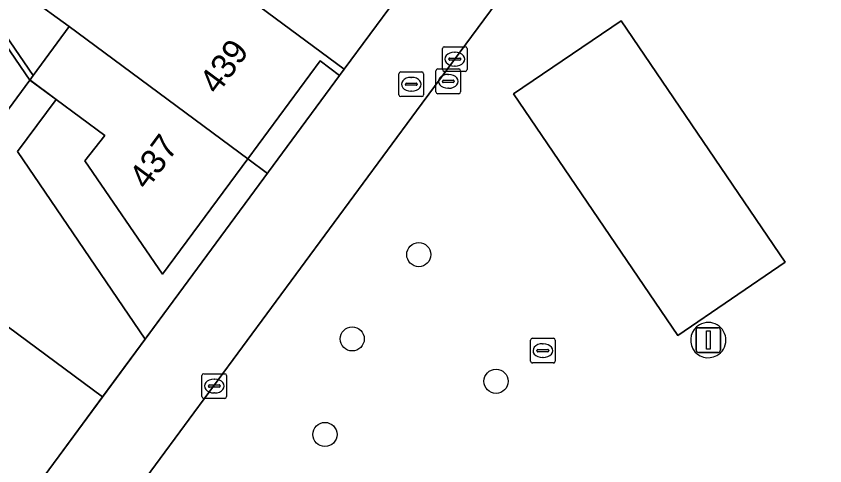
# Model space of a CAD drawing. Extents: x 155275 to 156265, y 382654 to 383635.
# Drawn here: x 155773.29 to 155806.09, y 383268.44 to 383286.66 of the extents above; entities that cross this region are included whole.
import ezdxf

# ---------------------------------------------------------------- set-up
doc = ezdxf.new("R2010")
doc.units = 0
for name, color, linetype in [('IMGEO_Boom', 7, 'Continuous'), ('IMGEO_Erf', 7, 'Continuous'), ('IMGEO_Kolk', 7, 'Continuous'), ('IMGEO_Lichtmast', 7, 'Continuous'), ('IMGEO_Muur', 7, 'Continuous'), ('IMGEO_Pand', 7, 'Continuous'), ('IMGEO_Pand_nummerreeks', 7, 'Continuous'), ('IMGEO_Pand_overbouw', 7, 'Continuous'), ('IMGEO_Parkeervlak_open', 7, 'Continuous'), ('IMGEO_Rijbaan_lokaal_open', 7, 'Continuous'), ('IMGEO_Rioolput', 7, 'Continuous'), ('IMGEO_Terreindeel_gesloten', 7, 'Continuous'), ('IMGEO_Voetpad_open', 7, 'Continuous')]:
    doc.layers.add(name, color=color, linetype=linetype)

msp = doc.modelspace()

# ---------------------------------------------------------------- linework, layer by layer
at = {"layer": 'IMGEO_Boom'}
for centre in [(155789.62, 383277), (155786.919, 383273.583), (155792.753, 383271.865), (155785.813, 383269.709)]:
    msp.add_circle(centre, 0.489, dxfattribs=at)
at = {"layer": 'IMGEO_Erf'}
msp.add_lwpolyline([(155766.346, 383295.405), (155773.979, 383284.258), (155775.431, 383286.243), (155773.822, 383287.426), (155776.948, 383291.655), (155780.069, 383295.876), (155783.19, 383300.098), (155786.313, 383304.323), (155789.463, 383308.585), (155792.614, 383312.847), (155795.763, 383317.106)], dxfattribs=at)
at = {"layer": 'IMGEO_Kolk'}
for p, q in [((155790.579, 383284.499), (155790.579, 383285.351)), ((155790.654, 383285.425), (155791.506, 383285.425)), ((155791.067, 383285.205), (155791.092, 383285.205)), ((155791.58, 383285.351), (155791.58, 383284.499)), ((155790.838, 383284.919), (155790.838, 383284.931)), ((155791.276, 383284.882), (155790.878, 383284.882)), ((155790.881, 383284.968), (155791.279, 383284.968)), ((155791.322, 383284.931), (155791.322, 383284.919)), ((155791.09, 383284.645), (155791.065, 383284.645)), ((155791.506, 383284.425), (155790.654, 383284.425)), ((155794.153, 383272.681), (155794.153, 383273.533)), ((155794.228, 383273.607), (155795.08, 383273.607)), ((155794.641, 383273.387), (155794.666, 383273.387)), ((155795.154, 383273.533), (155795.154, 383272.681)), ((155794.412, 383273.101), (155794.412, 383273.113)), ((155794.85, 383273.064), (155794.452, 383273.064)), ((155794.455, 383273.15), (155794.853, 383273.15)), ((155794.896, 383273.113), (155794.896, 383273.101)), ((155794.664, 383272.827), (155794.639, 383272.827)), ((155795.08, 383272.607), (155794.228, 383272.607)), ((155780.824, 383271.247), (155780.824, 383272.099)), ((155780.899, 383272.173), (155781.751, 383272.173)), ((155781.825, 383272.099), (155781.825, 383271.247)), ((155781.083, 383271.667), (155781.083, 383271.679)), ((155781.126, 383271.716), (155781.524, 383271.716)), ((155781.312, 383271.953), (155781.337, 383271.953)), ((155781.567, 383271.679), (155781.567, 383271.667)), ((155781.521, 383271.63), (155781.123, 383271.63)), ((155781.335, 383271.393), (155781.31, 383271.393)), ((155781.751, 383271.173), (155780.899, 383271.173))]:
    msp.add_line(p, q, dxfattribs=at)
for points in [[(155790.579, 383284.499), (155790.579, 383285.351)], [(155790.654, 383285.425), (155791.506, 383285.425)], [(155791.58, 383285.351), (155791.58, 383284.499)], [(155791.506, 383284.425), (155790.654, 383284.425)], [(155794.153, 383272.681), (155794.153, 383273.533)], [(155794.228, 383273.607), (155795.08, 383273.607)], [(155795.154, 383273.533), (155795.154, 383272.681)], [(155795.08, 383272.607), (155794.228, 383272.607)], [(155780.824, 383271.247), (155780.824, 383272.099)], [(155780.899, 383272.173), (155781.751, 383272.173)], [(155781.825, 383272.099), (155781.825, 383271.247)], [(155781.751, 383271.173), (155780.899, 383271.173)]]:
    msp.add_lwpolyline(points, dxfattribs=at)
for centre, radius, start, end in [((155790.656, 383285.349), 0.0765, 91.552, 178.448), ((155790.656, 383285.349), 0.0765, 91.552, 178.448), ((155791.504, 383285.349), 0.0765, 1.552, 88.448), ((155791.504, 383285.349), 0.0765, 1.552, 88.448), ((155790.878, 383284.928), 0.0403, 85.8775, 175.7526), ((155790.875, 383284.918), 0.0366, 178.938, 274.7102), ((155791.279, 383284.925), 0.043, 264.8664, 352.4533), ((155791.283, 383284.93), 0.0386, 1.7309, 96.639), ((155790.656, 383284.501), 0.0765, 181.552, 268.448), ((155790.656, 383284.501), 0.0765, 181.552, 268.448), ((155791.504, 383284.501), 0.0765, 271.552, 358.448), ((155791.504, 383284.501), 0.0765, 271.552, 358.448), ((155794.23, 383273.531), 0.0765, 91.552, 178.448), ((155794.23, 383273.531), 0.0765, 91.552, 178.448), ((155795.078, 383273.531), 0.0765, 1.552, 88.448), ((155795.078, 383273.531), 0.0765, 1.552, 88.448), ((155794.452, 383273.11), 0.0403, 85.8775, 175.7526), ((155794.449, 383273.1), 0.0366, 178.938, 274.7102), ((155794.853, 383273.107), 0.043, 264.8664, 352.4533), ((155794.857, 383273.112), 0.0386, 1.7309, 96.639), ((155794.23, 383272.683), 0.0765, 181.552, 268.448), ((155794.23, 383272.683), 0.0765, 181.552, 268.448), ((155795.078, 383272.683), 0.0765, 271.552, 358.448), ((155795.078, 383272.683), 0.0765, 271.552, 358.448), ((155780.901, 383272.097), 0.0765, 91.552, 178.448), ((155780.901, 383272.097), 0.0765, 91.552, 178.448), ((155781.749, 383272.097), 0.0765, 1.552, 88.448), ((155781.749, 383272.097), 0.0765, 1.552, 88.448), ((155781.123, 383271.676), 0.0403, 85.8775, 175.7526), ((155781.528, 383271.678), 0.0386, 1.7309, 96.639), ((155781.12, 383271.666), 0.0366, 178.938, 274.7102), ((155781.524, 383271.673), 0.043, 264.8664, 352.4533), ((155780.901, 383271.249), 0.0765, 181.552, 268.448), ((155780.901, 383271.249), 0.0765, 181.552, 268.448), ((155781.749, 383271.249), 0.0765, 271.552, 358.448), ((155781.749, 383271.249), 0.0765, 271.552, 358.448)]:
    msp.add_arc(centre, radius, start, end, dxfattribs=at)
for centre, major_axis, ratio, start_param, end_param in [((155791.066, 383284.925), (-0.387, 0.002), 0.722429, 4.712389, 7.853982), ((155791.091, 383284.925), (-0.39, 0.002), 0.717154, 1.570796, 4.712389), ((155794.64, 383273.107), (-0.387, 0.002), 0.722429, 4.712389, 7.853982), ((155794.665, 383273.107), (-0.39, 0.002), 0.717154, 1.570796, 4.712389), ((155781.311, 383271.673), (-0.387, 0.002), 0.722429, 4.712389, 7.853982), ((155781.336, 383271.673), (-0.39, 0.002), 0.717154, 1.570796, 4.712389)]:
    msp.add_ellipse(centre, major_axis=major_axis, ratio=ratio, start_param=start_param, end_param=end_param, dxfattribs=at)
at = {"layer": 'IMGEO_Lichtmast'}
for p, q in [((155800.969, 383274.036), (155801.759, 383274.036)), ((155801.759, 383274.036), (155800.969, 383274.036)), ((155800.869, 383273.136), (155800.869, 383273.936)), ((155800.869, 383273.936), (155800.869, 383273.136)), ((155801.859, 383273.936), (155801.859, 383273.136)), ((155801.859, 383273.136), (155801.859, 383273.936)), ((155801.759, 383273.036), (155800.969, 383273.036)), ((155800.969, 383273.036), (155801.759, 383273.036))]:
    msp.add_line(p, q, dxfattribs=at)
msp.add_lwpolyline([(155801.289, 383273.911), (155801.439, 383273.911), (155801.439, 383273.161), (155801.289, 383273.161), (155801.289, 383273.911)], dxfattribs=at)
for centre, start, end in [((155800.969, 383273.936), 90, 180), ((155800.969, 383273.936), 90, 180), ((155801.759, 383273.936), 0, 90), ((155801.759, 383273.936), 360, 90), ((155800.969, 383273.136), 180, 270), ((155800.969, 383273.136), 180, 270), ((155801.759, 383273.136), 270, 0), ((155801.759, 383273.136), 270, 0)]:
    msp.add_arc(centre, 0.1, start, end, dxfattribs=at)
at = {"layer": 'IMGEO_Muur'}
msp.add_lwpolyline([(155773.847, 383284.078), (155773.979, 383284.258), (155766.346, 383295.405), (155766.213, 383295.227)], close=True, dxfattribs=at)
at = {"layer": 'IMGEO_Pand'}
for points in [[(155789.72, 383288.742), (155780.069, 383295.876), (155776.948, 383291.655), (155786.598, 383284.52)], [(155775.431, 383286.243), (155782.682, 383280.882), (155785.615, 383284.849), (155786.405, 383284.259), (155786.598, 383284.52), (155776.948, 383291.655), (155773.822, 383287.426)], [(155775.431, 383286.243), (155773.979, 383284.258), (155773.847, 383284.078), (155774.904, 383283.294), (155776.886, 383281.823), (155776.079, 383280.798), (155779.225, 383276.207), (155782.682, 383280.882)]]:
    msp.add_lwpolyline(points, close=True, dxfattribs=at)
at = {"layer": 'IMGEO_Pand_overbouw'}
for points in [[(155782.682, 383280.882), (155783.479, 383280.293), (155786.405, 383284.259), (155785.615, 383284.849)], [(155776.886, 383281.823), (155774.904, 383283.294), (155773.836, 383284.086), (155768.735, 383277.191), (155776.792, 383271.232), (155783.479, 383280.293), (155782.682, 383280.882), (155779.225, 383276.207), (155776.079, 383280.798)], [(155771.65, 383264.258), (155776.792, 383271.232), (155768.735, 383277.191), (155762.039, 383268.14), (155762.867, 383267.527), (155766.131, 383271.951), (155766.263, 383272.13), (155769.629, 383267.192), (155768.939, 383266.259)]]:
    msp.add_lwpolyline(points, close=True, dxfattribs=at)
at = {"layer": 'IMGEO_Parkeervlak_open'}
msp.add_lwpolyline([(155797.829, 383286.482), (155793.468, 383283.515), (155800.125, 383273.728), (155804.486, 383276.694)], close=True, dxfattribs=at)
at = {"layer": 'IMGEO_Rijbaan_lokaal_open'}
msp.add_lwpolyline([(155849.638, 383246.563), (155829.44, 383276.11), (155811.913, 383301.75), (155819.677, 383316.264), (155817.087, 383320.059), (155811.131, 383312.082), (155798.256, 383294.644), (155789.533, 383282.828), (155777.762, 383266.885)], dxfattribs=at)
msp.add_lwpolyline([(155800.125, 383273.728), (155793.468, 383283.515), (155797.829, 383286.482), (155804.486, 383276.694)], close=True, dxfattribs=at)
for centre, start, end in [((155801.361, 383273.534), 119.6358, 299.1671), ((155801.364, 383273.536), 298.8814, 119.9215)]:
    msp.add_arc(centre, 0.714, start, end, dxfattribs=at)
at = {"layer": 'IMGEO_Rioolput'}
for p, q in [((155790.391, 383284.524), (155791.243, 383284.524)), ((155788.815, 383283.479), (155788.815, 383284.331)), ((155788.89, 383284.405), (155789.742, 383284.405)), ((155789.303, 383284.185), (155789.328, 383284.185)), ((155789.816, 383284.331), (155789.816, 383283.479)), ((155790.316, 383283.598), (155790.316, 383284.45)), ((155790.804, 383284.304), (155790.829, 383284.304)), ((155791.317, 383284.45), (155791.317, 383283.598)), ((155789.074, 383283.899), (155789.074, 383283.911)), ((155789.512, 383283.862), (155789.114, 383283.862)), ((155789.117, 383283.948), (155789.515, 383283.948)), ((155789.558, 383283.911), (155789.558, 383283.899)), ((155790.575, 383284.018), (155790.575, 383284.03)), ((155791.013, 383283.981), (155790.615, 383283.981)), ((155790.618, 383284.067), (155791.016, 383284.067)), ((155791.059, 383284.03), (155791.059, 383284.018)), ((155789.326, 383283.625), (155789.301, 383283.625)), ((155791.243, 383283.524), (155790.391, 383283.524)), ((155790.827, 383283.744), (155790.802, 383283.744)), ((155789.742, 383283.405), (155788.89, 383283.405))]:
    msp.add_line(p, q, dxfattribs=at)
for points in [[(155790.391, 383284.524), (155791.243, 383284.524)], [(155788.815, 383283.479), (155788.815, 383284.331)], [(155788.89, 383284.405), (155789.742, 383284.405)], [(155789.816, 383284.331), (155789.816, 383283.479)], [(155790.316, 383283.598), (155790.316, 383284.45)], [(155791.317, 383284.45), (155791.317, 383283.598)], [(155791.243, 383283.524), (155790.391, 383283.524)], [(155789.742, 383283.405), (155788.89, 383283.405)]]:
    msp.add_lwpolyline(points, dxfattribs=at)
for centre, radius, start, end in [((155790.393, 383284.448), 0.0765, 91.552, 178.448), ((155790.393, 383284.448), 0.0765, 91.552, 178.448), ((155791.241, 383284.448), 0.0765, 1.552, 88.448), ((155791.241, 383284.448), 0.0765, 1.552, 88.448), ((155788.892, 383284.329), 0.0765, 91.552, 178.448), ((155788.892, 383284.329), 0.0765, 91.552, 178.448), ((155789.74, 383284.329), 0.0765, 1.552, 88.448), ((155789.74, 383284.329), 0.0765, 1.552, 88.448), ((155789.114, 383283.908), 0.0403, 85.8775, 175.7526), ((155789.111, 383283.898), 0.0366, 178.938, 274.7102), ((155789.515, 383283.905), 0.043, 264.8664, 352.4533), ((155789.519, 383283.91), 0.0386, 1.7309, 96.639), ((155790.615, 383284.027), 0.0403, 85.8775, 175.7526), ((155790.612, 383284.017), 0.0366, 178.938, 274.7102), ((155791.016, 383284.024), 0.043, 264.8664, 352.4533), ((155791.02, 383284.029), 0.0386, 1.7309, 96.639), ((155788.892, 383283.481), 0.0765, 181.552, 268.448), ((155788.892, 383283.481), 0.0765, 181.552, 268.448), ((155789.74, 383283.481), 0.0765, 271.552, 358.448), ((155789.74, 383283.481), 0.0765, 271.552, 358.448), ((155790.393, 383283.6), 0.0765, 181.552, 268.448), ((155790.393, 383283.6), 0.0765, 181.552, 268.448), ((155791.241, 383283.6), 0.0765, 271.552, 358.448), ((155791.241, 383283.6), 0.0765, 271.552, 358.448)]:
    msp.add_arc(centre, radius, start, end, dxfattribs=at)
for centre, major_axis, ratio, start_param, end_param in [((155789.302, 383283.905), (-0.387, 0.002), 0.722429, 4.712389, 7.853982), ((155789.327, 383283.905), (-0.39, 0.002), 0.717154, 1.570796, 4.712389), ((155790.803, 383284.024), (-0.387, 0.002), 0.722429, 4.712389, 7.853982), ((155790.828, 383284.024), (-0.39, 0.002), 0.717154, 1.570796, 4.712389)]:
    msp.add_ellipse(centre, major_axis=major_axis, ratio=ratio, start_param=start_param, end_param=end_param, dxfattribs=at)
at = {"layer": 'IMGEO_Terreindeel_gesloten'}
for centre, start, end in [((155801.361, 383273.534), 119.6358, 299.1671), ((155801.364, 383273.536), 298.8814, 119.9215)]:
    msp.add_arc(centre, 0.714, start, end, dxfattribs=at)
at = {"layer": 'IMGEO_Voetpad_open'}
msp.add_lwpolyline([(155777.762, 383266.885), (155789.533, 383282.828), (155798.256, 383294.644), (155811.131, 383312.082), (155817.087, 383320.059), (155815.059, 383323.031), (155814.704, 383322.549), (155814.565, 383322.361), (155808.716, 383314.444), (155808.587, 383314.27), (155805.407, 383309.97), (155802.245, 383305.695), (155802.098, 383305.496), (155793.035, 383293.224), (155792.841, 383292.963), (155789.72, 383288.742), (155786.598, 383284.52), (155786.405, 383284.259), (155778.526, 383273.579), (155772.869, 383265.909)], dxfattribs=at)
for points in [[(155773.847, 383284.078), (155766.213, 383295.227), (155765.476, 383296.326), (155764.252, 383295.501), (155769.659, 383287.575), (155763.336, 383279.1), (155758.243, 383286.581), (155757.038, 383285.669), (155759.17, 383282.529), (155765.677, 383272.995)], [(155786.405, 383284.259), (155785.615, 383284.849), (155782.682, 383280.882), (155779.225, 383276.207), (155776.079, 383280.798), (155776.886, 383281.823), (155774.904, 383283.294), (155773.337, 383281.178), (155778.526, 383273.579)], [(155766.263, 383272.13), (155769.629, 383267.192), (155770.436, 383267.694), (155772.869, 383265.909), (155778.526, 383273.579), (155773.337, 383281.178), (155774.904, 383283.294), (155773.847, 383284.078), (155765.677, 383272.995)]]:
    msp.add_lwpolyline(points, close=True, dxfattribs=at)

# ---------------------------------------------------------------- texts
at = {"layer": 'IMGEO_Pand_nummerreeks'}
for s, p in [('439', (155781.445, 383283.447)), ('437', (155778.589, 383279.585))]:
    msp.add_text(s, height=1, rotation=53.5198, dxfattribs=at).set_placement(p)

doc.saveas('drawing.dxf')
